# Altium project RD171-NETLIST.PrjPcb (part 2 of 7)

## Sheet 3.SchDoc
size 420 x 297 mm
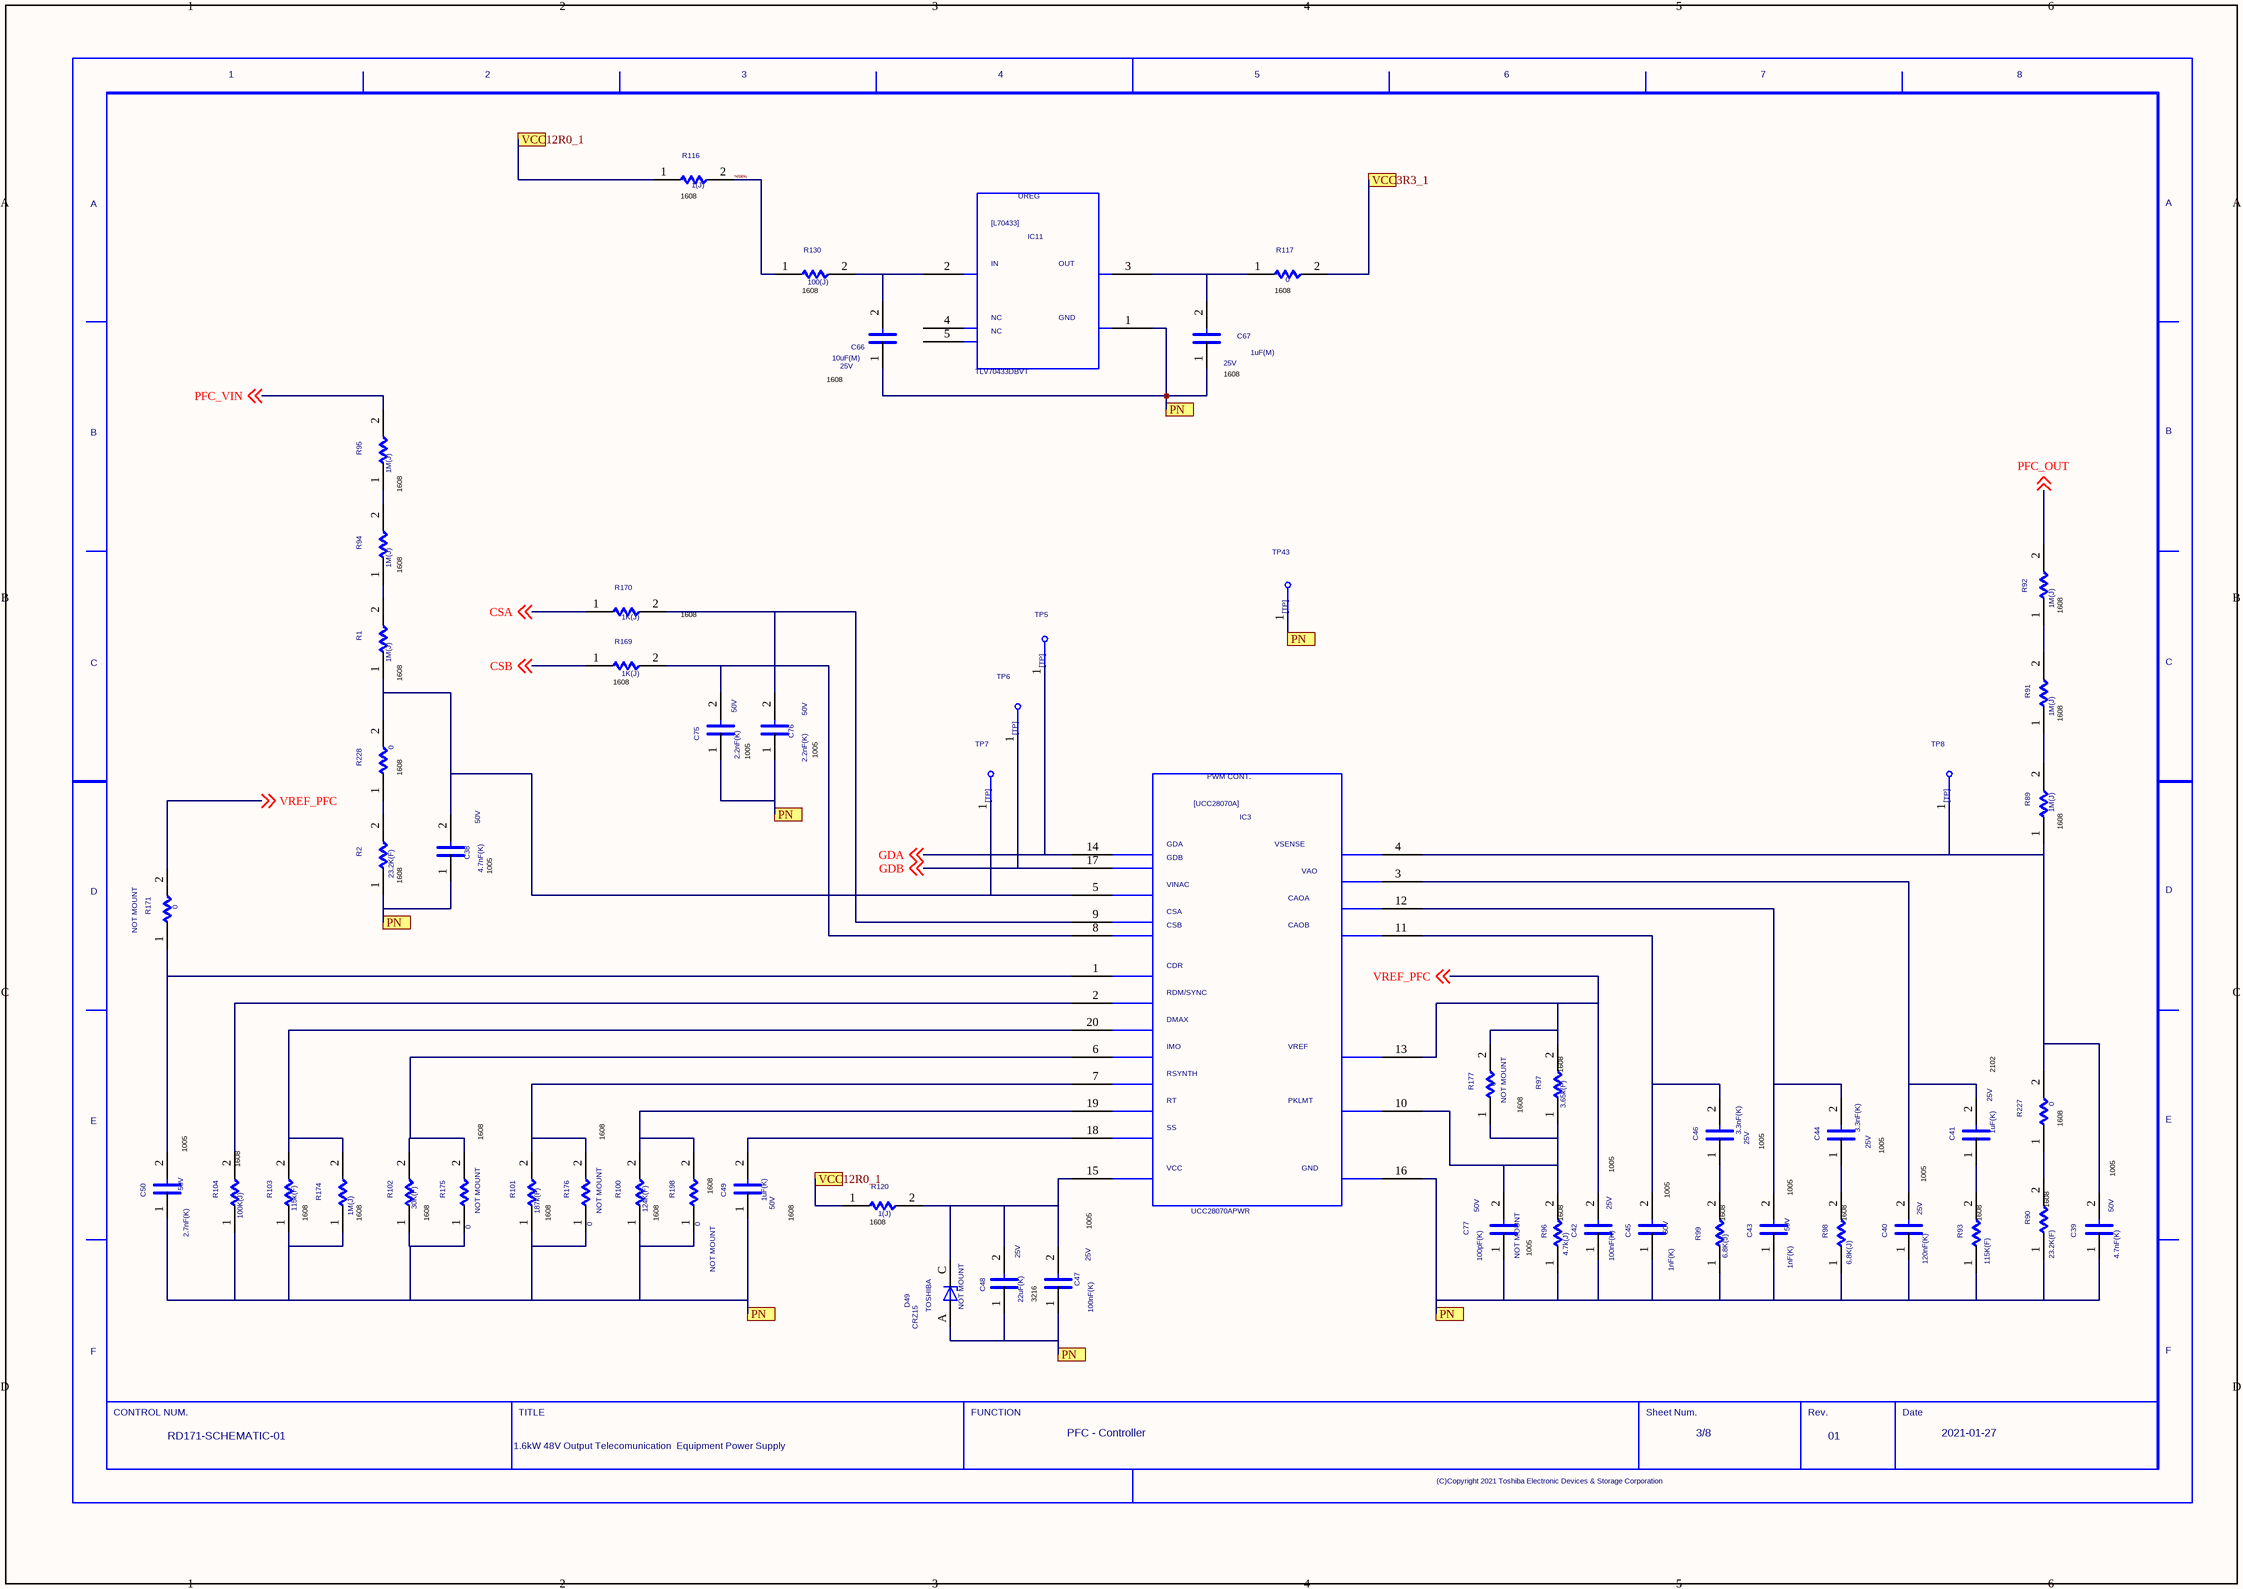
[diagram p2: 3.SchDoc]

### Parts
(Parts that share a designator on the sheet are numbered #1, #2 ... from top to bottom, then left to right.)
C38  VAL2: 50V  VAL1: 4.7nF(K)  (hidden comment: 4.7nF)
C39  VAL2: 50V  VAL1: 4.7nF(K)  (hidden comment: 4.7nF)
C40  VAL2: 25V  VAL1: 120nF(K)  (hidden comment: 120nF)
C41  VAL2: 25V  VAL1: 1uF(K)  (hidden comment: 1uF)
C42  VAL2: 25V  VAL1: 100nF(K)  (hidden comment: 100nF)
C43  VAL2: 50V  VAL1: 1nF(K)  (hidden comment: 1nF)
C44  VAL2: 25V  VAL1: 3.3nF(K)  (hidden comment: 3.3nF)
C45  VAL2: 50V  VAL1: 1nF(K)  (hidden comment: 1nF)
C46  VAL2: 25V  VAL1: 3.3nF(K)  (hidden comment: 3.3nF)
C47  VAL2: 25V  VAL1: 100nF(K)  (hidden comment: 100nF)
C48  VAL2: 25V  VAL1: 22uF(K)  (hidden comment: 22uF)
C49  VAL2: 50V  VAL1: 1uF(K)  [C1608JB1H105K080AB]  (hidden comment: 1uF)
C50  VAL2: 50V  VAL1: 2.7nF(K)  (hidden comment: 2.7nF)
C66  VAL2: 25V  VAL1: 10uF(M)  (hidden comment: 10uF)
C67  VAL2: 25V  VAL1: 1uF(M)  (hidden comment: 1uF)
C75  VAL2: 50V  VAL1: 2.2nF(K)  (hidden comment: 2.2nF)
C76  VAL2: 50V  VAL1: 2.2nF(K)  (hidden comment: 2.2nF)
C77  NOTMOUNT: NOT MOUNT  VAL2: 50V  VAL1: 100pF(K)  (hidden comment: 100pF)
D49  USERCOMPTEXT3: TOSHIBA  NOTMOUNT: NOT MOUNT  [CRZ15]  (hidden comment: D49)
IC3  IC3  [UCC28070APWR]  (value not drawn)
IC11  IC11  [TLV70433DBVT]  (value not drawn)
R1  VAL1: 1M(J)  (hidden comment: 1M)
R2  VAL1: 23.2K(F)  (hidden comment: 23.2K)
R89  VAL1: 1M(J)  (hidden comment: 1M)
R90  VAL1: 23.2K(F)  (hidden comment: 23.2K)
R91  VAL1: 1M(J)  (hidden comment: 1M)
R92  VAL1: 1M(J)  (hidden comment: 1M)
R93  VAL1: 115K(F)  (hidden comment: 115k)
R94  VAL1: 1M(J)  (hidden comment: 1M)
R95  VAL1: 1M(J)  (hidden comment: 1M)
R96  VAL1: 4.7k(J)  (hidden comment: 4.3k)
R97  VAL1: 3.65k(F)  (hidden comment: 3.65k)
R98  VAL1: 6.8K(J)  (hidden comment: 6.8k)
R99  VAL1: 6.8K(J)  (hidden comment: 6.8k)
R100  VAL1: 124K(F)  (hidden comment: 124k)
R101  VAL1: 187k(F)  (hidden comment: 187k)
R102  VAL1: 30K(F)  (hidden comment: 30k)
R103  VAL1: 115k(F)  (hidden comment: 115k)
R104  VAL1: 100K(J)  (hidden comment: 100k)
R116  VAL1: 1(J)  (hidden comment: 1)
R117  0
R120  VAL1: 1(J)  (hidden comment: 1)
R130  VAL1: 100(J)  (hidden comment: 100)
R169  VAL1: 1K(J)  (hidden comment: 1K)
R170  VAL1: 1K(J)  (hidden comment: 1K)
R171  NOTMOUNT: NOT MOUNT  (hidden comment: 0)
R174  VAL1: 1M(J)  (hidden comment: 1M)
R175  NOTMOUNT: NOT MOUNT  (hidden comment: 0)
R176  NOTMOUNT: NOT MOUNT  (hidden comment: 0)
R177  NOTMOUNT: NOT MOUNT  (hidden comment: 0)
R198  NOTMOUNT: NOT MOUNT  (hidden comment: 0)
R227  0
R228  0
TP5  TP5  [HK-2-S]  (value not drawn)
TP6  TP6  [HK-2-S]  (value not drawn)
TP7  TP7  [HK-2-S]  (value not drawn)
TP8  TP8  [HK-2-S]  (value not drawn)
TP43  TP43  [LC-22-S-WHITE]  (value not drawn)
U?#3  DATE: 2021-01-27  REVISION: 01  SHEETNUMBER: 3/8  FUNCTION: PFC - Controller  TITLE: 1.6kW 48V Output Telecomunication / Equipment Power Supply  DRAWINGNUMBER: RD171-SCHEMATIC-01  (hidden comment: WAKU_DEF100)

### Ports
PN, VCC3R3_1, VCC12R0_1

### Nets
$BN000001: R90.2 R227.1
$BN000002: R2.2 R228.1
CSA: R170.1 ; off-sheet CSA
CSB: R169.1 ; off-sheet CSB
GDA: IC3.14 TP5.1 ; off-sheet GDA
GDB: IC3.17 TP6.1 ; off-sheet GDB
N03591: R116.2 R130.1
PFC_OUT: R92.2 ; off-sheet PFC_OUT
PFC_VIN: R95.2 ; off-sheet PFC_VIN
SIG39: R89.2 R91.1
SIG40: R91.2 R92.1
SIG43: C45.2 C46.2 IC3.11
SIG44: C46.1 R99.2
SIG45: C43.2 C44.2 IC3.12
SIG46: C44.1 R98.2
SIG47: C40.2 C41.2 IC3.3
SIG48: C41.1 R93.2
SIG49: C39.2 IC3.4 R89.1 R227.2 TP8.1
SIG50: C49.2 IC3.18
SIG51: C50.2 IC3.1 R171.1
SIG52: IC3.19 R100.2 R198.2
SIG53: IC3.7 R101.2 R176.2
SIG54: IC3.6 R102.2 R175.2
SIG55: IC3.20 R103.2 R174.2
SIG56: IC3.2 R104.2
SIG60: R94.2 R95.1
SIG61: R1.2 R94.1
SIG62: C38.2 IC3.5 R1.1 R228.2 TP7.1
SIG86: C47.2 C48.2 D49.C IC3.15 R120.2
SIG185: C67.2 IC11.3 R117.1
SIG223: C66.2 IC11.2 R130.2
SIGN256: C77.2 IC3.10 R96.2 R97.1 R177.1
SIGN260: C76.2 IC3.9 R170.2
SIGN262: C75.2 IC3.8 R169.2
VREF_PFC: C42.2 IC3.13 R97.2 R171.2 R177.2 ; off-sheet VREF_PFC
NetC1_1: C38.1 C39.1 C40.1 C42.1 C43.1 C45.1 C47.1 C48.1 C49.1 C50.1 C66.1 C67.1 C75.1 C76.1 C77.1 D49.A IC3.16 IC11.1 R2.1 R90.1 R93.1 R96.1 R98.1 R99.1 R100.1 R101.1 R102.1 R103.1 R104.1 R174.1 R175.1 R176.1 R198.1 TP43.1 ; port PN
NetC70_2: R116.1 R120.1 ; port VCC12R0_1
NetC95_2: R117.2 ; port VCC3R3_1

Not connected (* = marked no-connect by the designer): IC11 4 5

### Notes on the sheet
- (near R116) 1608
- (near R130) 1608
- (near R117) 1608
- 1608
- (near C67) 1608
- (near R95) 1608
- (near R94) 1608
- (near R92) 1608
- (near R1) 1608
- (near R169) 1608
- (near R91) 1608
- (near R228) 1608
- 1005
- (near C76) 1005
- (near C38) 1005
- (near R89) 1608
- (near R2) 1608
- (near R97) 1608
- 2102
- (near R227) 1608
- (near C50) 1005
- (near R104) 1608
- (near R198) 1608
- (near C45) 1005
- (near C46) 1005
- (near C43) 1005
- (near C44) 1005
- (near R90) 1608
- (near C39) 1005
- (near R103) 1608
- (near R174) 1608
- (near R102) 1608
- (near R101) 1608
- (near R100) 1608
- (near C49) 1608
- (near R120) 1608
- (near R96) 1608
- (near R99) 1608
- (near R98) 1608
- (near R93) 1608
- 3216

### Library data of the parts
C38 = C: PARTNAME: Chip1005_GS_2; ORIGINALSYMBOLORIGIN: (0,0); TIME: 16:40:04; UPDATEUSER: t5459927; SAVECOUNT: 1; QUADMODEL: CON_1.2N; FUNCTION: C_C.Normal_package; NOMINALCAPACITA: 1.2n; RATEDVOLTAGE: 50; CDMASTERCADCELG: KC0005; MAKER: TDK; TEMPCHARACTERI2: B; SIZECODESMD: 1005; OUMEMAKER: TYD 太陽誘電; COMP: PRT_52; ADSMODELNAME: s_UMK105BJ122KV_F; PMPRODUCTSTYPEG: HD1; FNLEADFREETHET1GT2GMCTH1: 2_0_N; VAL3: GRM155R71H472JA01D; CAPACITANCETOLE: K; OUMECLASSIFICATION: セラミックコンデンサ; OUMEMAKERKATAMEI: UMK105BJ122KV-F; INSTANCENAME: INS2671
C39 = C: PARTNAME: Chip1005_GS_2; ORIGINALSYMBOLORIGIN: (0,0); TIME: 16:40:04; UPDATEUSER: t5459927; SAVECOUNT: 1; QUADMODEL: CON_1.2N; FUNCTION: C_C.Normal_package; NOMINALCAPACITA: 1.2n; RATEDVOLTAGE: 50; CDMASTERCADCELG: KC0005; MAKER: TDK; TEMPCHARACTERI2: B; SIZECODESMD: 1005; OUMEMAKER: TYD 太陽誘電; COMP: PRT_52; ADSMODELNAME: s_UMK105BJ122KV_F; PMPRODUCTSTYPEG: HD1; FNLEADFREETHET1GT2GMCTH1: 2_0_N; VAL3: GRM155R71H472JA01D; CAPACITANCETOLE: K; OUMECLASSIFICATION: セラミックコンデンサ; OUMEMAKERKATAMEI: UMK105BJ122KV-F; INSTANCENAME: INS2681
C40 = C: PARTNAME: Chip1608_GS_1; ORIGINALSYMBOLORIGIN: (0,0); TIME: 16:40:04; UPDATEUSER: t5459927; SAVECOUNT: 1; QUADMODEL: CON_150N; FUNCTION: C_C.Normal_package; NOMINALCAPACITA: 150n; RATEDVOLTAGE: 25; CDMASTERCADCELG: KC0008; MAKER: MURATA; SIZECODESMD: 1608; OUMEMAKER: MRT 村田製作所; COMP: PRT_48; ADSMODELNAME: s_GCM188R71E154KA37D; PMPRODUCTSTYPEG: DME; FNLEADFREETHET1GT2GMCTH1: N_N_N; VAL3: GRM188R71E124KA01D; CAPACITANCETOLE: K; OUMECLASSIFICATION: セラミックコンデンサ; OUMEMAKERKATAMEI: GCM188R71E154KA37D; INSTANCENAME: INS2519
C41 = C: PARTNAME: Chip2012_GS_1; ORIGINALSYMBOLORIGIN: (0,0); TIME: 16:40:04; UPDATEUSER: t5459927; SAVECOUNT: 1; COMPONENTNAME: C_C.Normal_package; RATEDVOLTAGE: 50; ADSMODELNAME: s_GCM31CR71H155KA55L; CAPACITANCETOLE: K; NOMINALCAPACITA: 1.5u; VAL3: C2012X7R1E105K125AB; MAKER: TDK; PMPRODUCTSTYPEG: DME; COMP: PRT_32; CHIPSIZE: 2012; INSTANCENAME: INS2529
C42 = C: PARTNAME: Chip1005_GS_2; ORIGINALSYMBOLORIGIN: (0,0); TIME: 16:40:04; UPDATEUSER: t5459927; SAVECOUNT: 1; QUADMODEL: CON_100N; FUNCTION: C_C.Normal_package; NOMINALCAPACITA: 100n; RATEDVOLTAGE: 25; CDMASTERCADCELG: KC0005; MAKER: TDK; SIZECODESMD: 1005; OUMEMAKER: MRT 村田製作所; COMP: PRT_52; ADSMODELNAME: s_GRM155R71E104KE14D; FNLEADFREETHET1GT2GMCTH1: N_N_N; VAL3: C1005X7R1E104K050BB; CAPACITANCETOLE: K; OUMECLASSIFICATION: セラミックコンデンサ; OUMEMAKERKATAMEI: GRM155R71E104KE14D; INSTANCENAME: INS2499
C43 = C: PARTNAME: Chip1005_GS_2; ORIGINALSYMBOLORIGIN: (0,0); TIME: 16:40:04; UPDATEUSER: t5459927; SAVECOUNT: 1; QUADMODEL: CON_1N; FUNCTION: C_C.Normal_package; NOMINALCAPACITA: 1n; RATEDVOLTAGE: 50; CDMASTERCADCELG: KC0005; MAKER: TDK; TEMPCHARACTERI2: B; SIZECODESMD: 1005; OUMEMAKER: TYD 太陽誘電; COMP: PRT_52; ADSMODELNAME: s_UMK105BJ102KV_F; PMPRODUCTSTYPEG: HD1-PC1; FNLEADFREETHET1GT2GMCTH1: 2_0_N; VAL3: UMK105BJ102KV-F; CAPACITANCETOLE: K; OUMECLASSIFICATION: セラミックコンデンサ; INSTANCENAME: INS2651
C44 = C: PARTNAME: Chip1005_GS_2; ORIGINALSYMBOLORIGIN: (0,0); TIME: 16:40:04; UPDATEUSER: t5459927; SAVECOUNT: 1; QUADMODEL: CON_3.3N; FUNCTION: C_C.Normal_package; NOMINALCAPACITA: 3.3n; RATEDVOLTAGE: 25; CDMASTERCADCELG: KC0005; MAKER: TDK; SIZECODESMD: 1005; OUMEMAKER: TDK ＴＤＫ; COMP: PRT_52; ADSMODELNAME: s_C1005JB1E332KT; FNLEADFREETHET1GT2GMCTH1: N_N_N; VAL3: CGJ2B2X7R1E332K050BA; CAPACITANCETOLE: K; OUMECLASSIFICATION: セラミックコンデンサ; OUMEMAKERKATAMEI: C1005JB1E332KT; INSTANCENAME: INS2893
C45 = C: PARTNAME: Chip1005_GS_2; ORIGINALSYMBOLORIGIN: (0,0); TIME: 16:40:04; UPDATEUSER: t5459927; SAVECOUNT: 1; QUADMODEL: CON_1N; FUNCTION: C_C.Normal_package; NOMINALCAPACITA: 1n; RATEDVOLTAGE: 50; CDMASTERCADCELG: KC0005; MAKER: TDK; TEMPCHARACTERI2: B; SIZECODESMD: 1005; OUMEMAKER: TYD 太陽誘電; COMP: PRT_52; ADSMODELNAME: s_UMK105BJ102KV_F; PMPRODUCTSTYPEG: HD1-PC1; FNLEADFREETHET1GT2GMCTH1: 2_0_N; VAL3: UMK105BJ102KV-F; CAPACITANCETOLE: K; OUMECLASSIFICATION: セラミックコンデンサ; INSTANCENAME: INS2661
C46 = C: PARTNAME: Chip1005_GS_2; ORIGINALSYMBOLORIGIN: (0,0); TIME: 16:40:04; UPDATEUSER: t5459927; SAVECOUNT: 1; QUADMODEL: CON_3.3N; FUNCTION: C_C.Normal_package; NOMINALCAPACITA: 3.3n; RATEDVOLTAGE: 25; CDMASTERCADCELG: KC0005; MAKER: TDK; SIZECODESMD: 1005; OUMEMAKER: TDK ＴＤＫ; COMP: PRT_52; ADSMODELNAME: s_C1005JB1E332KT; FNLEADFREETHET1GT2GMCTH1: N_N_N; VAL3: CGJ2B2X7R1E332K050BA; CAPACITANCETOLE: K; OUMECLASSIFICATION: セラミックコンデンサ; OUMEMAKERKATAMEI: C1005JB1E332KT; INSTANCENAME: INS2883
C47 = C: PARTNAME: Chip1005_GS_2; ORIGINALSYMBOLORIGIN: (0,0); TIME: 16:40:04; UPDATEUSER: t5459927; SAVECOUNT: 1; QUADMODEL: CON_100N; FUNCTION: C_C.Normal_package; NOMINALCAPACITA: 100n; RATEDVOLTAGE: 25; CDMASTERCADCELG: KC0005; MAKER: TDK; SIZECODESMD: 1005; OUMEMAKER: MRT 村田製作所; ADSCNVFLAG: ON; ADSCOMPONENTNAME: C_1005; COMP: PRT_52; ADSMODELNAME: s_GRM155R71E104KE14D; FNLEADFREETHET1GT2GMCTH1: N_N_N; VAL3: C1005X7R1E104K050BB; CAPACITANCETOLE: K; OUMECLASSIFICATION: セラミックコンデンサ; OUMEMAKERKATAMEI: GRM155R71E104KE14D; INSTANCENAME: INS2489
C48 = C: PARTNAME: Chip3216_GS_1; ORIGINALSYMBOLORIGIN: (0,0); TIME: 16:40:04; UPDATEUSER: t5459927; SAVECOUNT: 1; QUADMODEL: CON_22U; FUNCTION: C_C.Normal_package; NOMINALCAPACITA: 22u; RATEDVOLTAGE: 25; CDMASTERCADCELG: KC0014; MAKER: MURATA; TEMPCHARACTERI2: B; SIZECODESMD: 3216; OUMEMAKER: MRT 村田製作所; COMP: PRT_51; ADSMODELNAME: s_GRM31CB31E226ME15D; FNLEADFREETHET1GT2GMCTH1: N_N_N; VAL3: GRM31CR61E226KE15L; CAPACITANCETOLE: M; OUMECLASSIFICATION: セラミックコンデンサ; OUMEMAKERKATAMEI: GRM31CB31E226ME15D; INSTANCENAME: INS2863
C49 = C: PARTNAME: Chip1608_GS_1; ORIGINALSYMBOLORIGIN: (0,0); TIME: 16:40:04; UPDATEUSER: t5459927; SAVECOUNT: 1; QUADMODEL: CON_100N; FUNCTION: C_C.Normal_package; NOMINALCAPACITA: 100n; RATEDVOLTAGE: 25; CDMASTERCADCELG: KC0005; MAKER: TDK; SIZECODESMD: 1005; OUMEMAKER: MRT 村田製作所; COMP: PRT_52; ADSMODELNAME: s_GRM155R71E104KE14D; FNLEADFREETHET1GT2GMCTH1: N_N_N; CAPACITANCETOLE: K; OUMECLASSIFICATION: セラミックコンデンサ; OUMEMAKERKATAMEI: GRM155R71E104KE14D; INSTANCENAME: INS2479
C50 = C: PARTNAME: Chip1005_GS_2; ORIGINALSYMBOLORIGIN: (0,0); TIME: 16:40:04; UPDATEUSER: t5459927; SAVECOUNT: 1; QUADMODEL: CON_2.7N; FUNCTION: C_C.Normal_package; NOMINALCAPACITA: 2.7n; RATEDVOLTAGE: 50; CDMASTERCADCELG: DC834K; MAKER: TDK; TEMPCHARACTERI2: B; SIZECODESMD: 1005; OUMEMAKER: TYD 太陽誘電; COMP: PRT_52; ADSMODELNAME: s_UMK105BJ272KV_F; PMPRODUCTSTYPEG: PC1; FNLEADFREETHET1GT2GMCTH1: 3_0_N; VAL3: UMK105BJ272KV-F; CAPACITANCETOLE: K; OUMECLASSIFICATION: セラミックコンデンサ; INSTANCENAME: INS2711
C66 = C: PARTNAME: Chip1608_GS_1; ORIGINALSYMBOLORIGIN: (0,0); TIME: 16:40:04; UPDATEUSER: t5459927; SAVECOUNT: 1; QUADMODEL: CON_10U; FUNCTION: C_C.Normal_package; NOMINALCAPACITA: 10u; RATEDVOLTAGE: 25; CDMASTERCADCELG: KC0167; MAKER: TDK; SIZECODESMD: 1608; OUMEMAKER: MRT 村田製作所; COMP: PRT_48; ADSMODELNAME: s_ZRB18AR61E106ME01L; FNLEADFREETHET1GT2GMCTH1: N_N_N; VAL3: C1608X5R1E106M080AC; CAPACITANCETOLE: M; OUMECLASSIFICATION: セラミックコンデンサ; OUMEMAKERKATAMEI: ZRB18AR61E106ME01L; INSTANCENAME: INS2953
C67 = C: PARTNAME: Chip1005_GS_2; ORIGINALSYMBOLORIGIN: (0,0); TIME: 16:40:04; UPDATEUSER: t5459927; SAVECOUNT: 1; QUADMODEL: CON_1U; FUNCTION: C_C.Normal_package; NOMINALCAPACITA: 1u; RATEDVOLTAGE: 25; CDMASTERCADCELG: KC0008; MAKER: TDK; TEMPCHARACTERI2: B; SIZECODESMD: 1608; OUMEMAKER: MRT 村田製作所; ADSCNVFLAG: ON; ADSCOMPONENTNAME: C_1608; COMP: PRT_52; ADSMODELNAME: s_GRM185B31E105KA12D; PMPRODUCTSTYPEG: HD1; FNLEADFREETHET1GT2GMCTH1: N_N_N; VAL3: C1005X5R1E105M050BC; CAPACITANCETOLE: K; OUMECLASSIFICATION: セラミックコンデンサ; OUMEMAKERKATAMEI: GRM185B31E105KA12D; CHIPSIZE: 1005; INSTANCENAME: INS2963
C75 = C: PARTNAME: Chip1005_GS_2; ORIGINALSYMBOLORIGIN: (0,0); TIME: 16:40:04; UPDATEUSER: t5459927; SAVECOUNT: 1; QUADMODEL: CON_2.2N; FUNCTION: C_C.Normal_package; NOMINALCAPACITA: 2.2n; RATEDVOLTAGE: 50; CDMASTERCADCELG: KC0005; MAKER: TDK; TEMPCHARACTERI2: B; SIZECODESMD: 1005; OUMEMAKER: TYD 太陽誘電; COMP: PRT_52; ADSMODELNAME: s_UMK105BJ222KV_F; PMPRODUCTSTYPEG: HD1-PC1; FNLEADFREETHET1GT2GMCTH1: 2_0_N; VAL3: UMK105BJ222KV-F; CAPACITANCETOLE: K; OUMECLASSIFICATION: セラミックコンデンサ; INSTANCENAME: INS2691
C76 = C: PARTNAME: Chip1005_GS_2; ORIGINALSYMBOLORIGIN: (0,0); TIME: 16:40:04; UPDATEUSER: t5459927; SAVECOUNT: 1; QUADMODEL: CON_2.2N; FUNCTION: C_C.Normal_package; NOMINALCAPACITA: 2.2n; RATEDVOLTAGE: 50; CDMASTERCADCELG: KC0005; MAKER: TDK; OLDCOMPONENTID: 99; TEMPCHARACTERI2: B; SIZECODESMD: 1005; OUMEMAKER: TYD 太陽誘電; COMP: PRT_52; ADSMODELNAME: s_UMK105BJ222KV_F; PMPRODUCTSTYPEG: HD1-PC1; FNLEADFREETHET1GT2GMCTH1: 2_0_N; VAL3: UMK105BJ222KV-F; CAPACITANCETOLE: K; OUMECLASSIFICATION: セラミックコンデンサ; INSTANCENAME: INS2701
C77 = C: PARTNAME: Chip1608_GS_1; ORIGINALSYMBOLORIGIN: (0,0); TIME: 16:40:04; UPDATEUSER: t5459927; SAVECOUNT: 1; COMP: PRT_48; CHIPSIZE: 1608; FUNCTION: C_C.Normal_package; VAL3: GRM1885C1H101JA01D; MAKER: MURATA; INSTANCENAME: INS2539
D49 = ZD: PARTNAME: CRZ15_TS_A; OUMEPARTTYPE: D; UPDATEUSER: t5459927; UPDATETIME: 16:40:05; SAVECOUNT: 1; SAVEAREA0: -4630,-153,17114,13055; ORIGINALSYMBOLORIGIN: (0,0); FUNCTION: ZD_ZD.Normal_package; CDMASTERCADCELG: MMK0167; FORWARDVOLTAGEM: 0; OUMEMAKER: TSB 東芝; MOUNTINGFORMSMD: SMD; COMP: PRT_6; ADSMODELNAME: s_CRZ15; FNLEADFREETHET1GT2GMCTH1: N_N_N; ZENERVOLTAGEMAX: 16.5; OUMECLASSIFICATION: 定電圧ダイオード; INSTANCENAME: INS2465
IC3 = L28070: PARTNAME: UCC28070APW_TI; UPDATEUSER: t5459927; UPDATETIME: 16:40:04; SAVECOUNT: 1; SAVEAREA0: -70831,-61057,118891,26398; ORIGINALSYMBOLORIGIN: (0,0); COMP: PRT_59; FUNCTION: L28070_L28070.Normal_package; MAKER: TEXAS; INSTANCENAME: INS2419
IC11 = L70433: PARTNAME: TLV70433DBVT_TI; UPDATEUSER: t5459927; UPDATETIME: 16:40:04; SAVECOUNT: 1; SAVEAREA0: -25132,-24804,51942,10724; ORIGINALSYMBOLORIGIN: (0,0); COMP: PRT_10; FUNCTION: L70433_L70433.Normal_package; MAKER: TEXAS; INSTANCENAME: INS3049
R1 = R: PARTNAME: Chip1608_GS_1; ORIGINALSYMBOLORIGIN: (0,0); TIME: 16:40:04; UPDATEUSER: t5459927; SAVECOUNT: 1; QUADMODEL: RES_1M; FUNCTION: R_R.Normal_package; CDMASTERCADCELG: KC0167; MAKER: KOA; RESISTANCETOLER: F; SIZECODESMD: 1608; OUMEMAKER: KOA コーア; POWERRATING: 100m; MOUNTINGFORMSMD: SMD; COMP: PRT_8; ADSMODELNAME: s_RK73H1JTTD1004F; FNLEADFREETHET1GT2GMCTH1: N_N_N; VAL3: RK73B1JTTD105J; VAL2: 100mW,±5%; OUMECLASSIFICATION: 表面実装用固定抵抗器; OUMEMAKERKATAMEI: RK73H1JTTD1004F; INSTANCENAME: INS2763
R2 = R: PARTNAME: Chip1608_GS_1; ORIGINALSYMBOLORIGIN: (0,0); TIME: 16:40:04; UPDATEUSER: t5459927; SAVECOUNT: 1; QUADMODEL: RES_24K; FUNCTION: R_R.Normal_package; CDMASTERCADCELG: KC0008; MAKER: PANASONIC; RESISTANCETOLER: J; SIZECODESMD: 1608; OUMEMAKER: NAE パナソニックエレクトロニックデバイス; POWERRATING: 63m; MOUNTINGFORMSMD: SMD; NOMINALRESISTAN: 24K; COMP: PRT_8; ADSMODELNAME: s_ERJ3GEYJ243V; FNLEADFREETHET1GT2GMCTH1: 3_1_N; VAL3: ERJ-3EKF2322V; VAL2: 100mW,±1%; OUMECLASSIFICATION: 表面実装用固定抵抗器; OUMEMAKERKATAMEI: ERJ3GEYJ243V; INSTANCENAME: INS2773
R89 = R: PARTNAME: Chip1608_GS_1; ORIGINALSYMBOLORIGIN: (0,0); TIME: 16:40:04; UPDATEUSER: t5459927; SAVECOUNT: 1; QUADMODEL: RES_1M; FUNCTION: R_R.Normal_package; CDMASTERCADCELG: KC0167; MAKER: KOA; RESISTANCETOLER: F; SIZECODESMD: 1608; OUMEMAKER: KOA コーア; POWERRATING: 100m; MOUNTINGFORMSMD: SMD; COMP: PRT_8; ADSMODELNAME: s_RK73H1JTTD1004F; FNLEADFREETHET1GT2GMCTH1: N_N_N; VAL3: RK73B1JTTD105J; VAL2: 100mW; OUMECLASSIFICATION: 表面実装用固定抵抗器; OUMEMAKERKATAMEI: RK73H1JTTD1004F; INSTANCENAME: INS2813
R90 = R: PARTNAME: Chip1608_GS_1; ORIGINALSYMBOLORIGIN: (0,0); TIME: 16:40:04; UPDATEUSER: t5459927; SAVECOUNT: 1; QUADMODEL: RES_22K; FUNCTION: R_R.Normal_package; CDMASTERCADCELG: KC0008; MAKER: PANASONIC; RESISTANCETOLER: F; SIZECODESMD: 1608; OUMEMAKER: NAE パナソニックエレクトロニックデバイス; POWERRATING: 100m; MOUNTINGFORMSMD: SMD; NOMINALRESISTAN: 22K; COMP: PRT_8; ADSMODELNAME: s_ERJ3EKF2202V; FNLEADFREETHET1GT2GMCTH1: N_N_N; VAL3: ERJ-3EKF2322V; VAL2: 100mW,±1%; OUMECLASSIFICATION: 表面実装用固定抵抗器; OUMEMAKERKATAMEI: ERJ3EKF2202V; INSTANCENAME: INS2923
R91 = R: PARTNAME: Chip1608_GS_1; ORIGINALSYMBOLORIGIN: (0,0); TIME: 16:40:04; UPDATEUSER: t5459927; SAVECOUNT: 1; QUADMODEL: RES_1M; FUNCTION: R_R.Normal_package; CDMASTERCADCELG: KC0167; MAKER: KOA; RESISTANCETOLER: F; SIZECODESMD: 1608; OUMEMAKER: KOA コーア; POWERRATING: 100m; MOUNTINGFORMSMD: SMD; COMP: PRT_8; ADSMODELNAME: s_RK73H1JTTD1004F; FNLEADFREETHET1GT2GMCTH1: N_N_N; VAL3: RK73B1JTTD105J; VAL2: 100mW,±5%; OUMECLASSIFICATION: 表面実装用固定抵抗器; OUMEMAKERKATAMEI: RK73H1JTTD1004F; INSTANCENAME: INS2803
R92 = R: PARTNAME: Chip1608_GS_1; ORIGINALSYMBOLORIGIN: (0,0); TIME: 16:40:04; UPDATEUSER: t5459927; SAVECOUNT: 1; QUADMODEL: RES_1M; FUNCTION: R_R.Normal_package; CDMASTERCADCELG: KC0167; MAKER: KOA; RESISTANCETOLER: F; SIZECODESMD: 1608; OUMEMAKER: KOA コーア; POWERRATING: 100m; MOUNTINGFORMSMD: SMD; COMP: PRT_8; ADSMODELNAME: s_RK73H1JTTD1004F; FNLEADFREETHET1GT2GMCTH1: N_N_N; VAL3: RK73B1JTTD105J; VAL2: 100mW,±5%; OUMECLASSIFICATION: 表面実装用固定抵抗器; OUMEMAKERKATAMEI: RK73H1JTTD1004F; INSTANCENAME: INS2823
R93 = R: PARTNAME: Chip1608_GS_1; ORIGINALSYMBOLORIGIN: (0,0); TIME: 16:40:04; UPDATEUSER: t5459927; SAVECOUNT: 1; QUADMODEL: RES_110K; FUNCTION: R_R.Normal_package; CDMASTERCADCELG: KC0008; MAKER: PANASONIC; RESISTANCETOLER: F; SIZECODESMD: 1608; OUMEMAKER: NAE パナソニックエレクトロニックデバイス; POWERRATING: 100m; MOUNTINGFORMSMD: SMD; NOMINALRESISTAN: 110K; COMP: PRT_8; ADSMODELNAME: s_ERJ3EKF1103V; FNLEADFREETHET1GT2GMCTH1: N_N_N; VAL3: ERJ-3EKF1153V; VAL2: 100mW,±1%; OUMECLASSIFICATION: 表面実装用固定抵抗器; OUMEMAKERKATAMEI: ERJ3EKF1103V; INSTANCENAME: INS2913
R94 = R: PARTNAME: Chip1608_GS_1; ORIGINALSYMBOLORIGIN: (0,0); TIME: 16:40:04; UPDATEUSER: t5459927; SAVECOUNT: 1; QUADMODEL: RES_1M; FUNCTION: R_R.Normal_package; CDMASTERCADCELG: KC0167; MAKER: KOA; RESISTANCETOLER: F; SIZECODESMD: 1608; OUMEMAKER: KOA コーア; POWERRATING: 100m; MOUNTINGFORMSMD: SMD; COMP: PRT_8; ADSMODELNAME: s_RK73H1JTTD1004F; FNLEADFREETHET1GT2GMCTH1: N_N_N; VAL3: RK73B1JTTD105J; VAL2: 100mW,±5%; OUMECLASSIFICATION: 表面実装用固定抵抗器; OUMEMAKERKATAMEI: RK73H1JTTD1004F; INSTANCENAME: INS2743
R95 = R: PARTNAME: Chip1608_GS_1; ORIGINALSYMBOLORIGIN: (0,0); TIME: 16:40:04; UPDATEUSER: t5459927; SAVECOUNT: 1; QUADMODEL: RES_1M; FUNCTION: R_R.Normal_package; CDMASTERCADCELG: KC0167; MAKER: KOA; RESISTANCETOLER: F; SIZECODESMD: 1608; OUMEMAKER: KOA コーア; POWERRATING: 100m; MOUNTINGFORMSMD: SMD; COMP: PRT_8; ADSMODELNAME: s_RK73H1JTTD1004F; FNLEADFREETHET1GT2GMCTH1: N_N_N; VAL3: RK73B1JTTD105J; VAL2: 100mW,±5%; OUMECLASSIFICATION: 表面実装用固定抵抗器; OUMEMAKERKATAMEI: RK73H1JTTD1004F; INSTANCENAME: INS2753
R96 = R: PARTNAME: Chip1608_GS_1; ORIGINALSYMBOLORIGIN: (0,0); TIME: 16:40:04; UPDATEUSER: t5459927; SAVECOUNT: 1; COMP: PRT_8; CHIPSIZE: 1608; FUNCTION: R_R.Normal_package; VAL3: RK73B1JTTD392J; VAL2: 100mW,±5%; MAKER: KOA; INSTANCENAME: INS2571
R97 = R: PARTNAME: Chip1608_GS_1; ORIGINALSYMBOLORIGIN: (0,0); TIME: 16:40:04; UPDATEUSER: t5459927; SAVECOUNT: 1; COMP: PRT_8; CHIPSIZE: 1608; FUNCTION: R_R.Normal_package; VAL3: ERJ-3EKF3651V; VAL2: 100mW,±1%; MAKER: PANASONIC; INSTANCENAME: INS2561
R98 = R: PARTNAME: Chip1608_GS_1; ORIGINALSYMBOLORIGIN: (0,0); TIME: 16:40:04; UPDATEUSER: t5459927; SAVECOUNT: 1; QUADMODEL: RES_6.8K; FUNCTION: R_R.Normal_package; CDMASTERCADCELG: KCK0203; MAKER: KOA; RESISTANCETOLER: B; SIZECODESMD: 1608; OUMEMAKER: KOA コーア; POWERRATING: 100m; MOUNTINGFORMSMD: SMD; COMP: PRT_8; ADSMODELNAME: s_RN73H1JTTD6801B10; PMPRODUCTSTYPEG: DME; FNLEADFREETHET1GT2GMCTH1: N_N_N; VAL3: RK73B1JTTD682J; VAL2: 100mW,±5%; OUMECLASSIFICATION: 表面実装用固定抵抗器; OUMEMAKERKATAMEI: RN73H1JTTD6801B10; INSTANCENAME: INS2903
R99 = R: PARTNAME: Chip1608_GS_1; ORIGINALSYMBOLORIGIN: (0,0); TIME: 16:40:04; UPDATEUSER: t5459927; SAVECOUNT: 1; QUADMODEL: RES_6.8K; FUNCTION: R_R.Normal_package; CDMASTERCADCELG: KCK0203; MAKER: KOA; RESISTANCETOLER: B; SIZECODESMD: 1608; OUMEMAKER: KOA コーア; POWERRATING: 100m; MOUNTINGFORMSMD: SMD; COMP: PRT_8; ADSMODELNAME: s_RN73H1JTTD6801B10; PMPRODUCTSTYPEG: DME; FNLEADFREETHET1GT2GMCTH1: N_N_N; VAL3: RK73B1JTTD682J; VAL2: 100mW,±5%; OUMECLASSIFICATION: 表面実装用固定抵抗器; OUMEMAKERKATAMEI: RN73H1JTTD6801B10; INSTANCENAME: INS2873
R100 = R: PARTNAME: Chip1608_GS_1; ORIGINALSYMBOLORIGIN: (0,0); TIME: 16:40:04; UPDATEUSER: t5459927; SAVECOUNT: 1; QUADMODEL: RES_120K; FUNCTION: R_R.Normal_package; CDMASTERCADCELG: KC0008; MAKER: PANASONIC; RESISTANCETOLER: F; SIZECODESMD: 1608; OUMEMAKER: NAE パナソニックエレクトロニックデバイス; POWERRATING: 100m; MOUNTINGFORMSMD: SMD; NOMINALRESISTAN: 120K; COMP: PRT_8; ADSMODELNAME: s_ERJ3EKF1203V; FNLEADFREETHET1GT2GMCTH1: N_N_N; VAL3: ERJ-3EKF1243V; VAL2: 100mW,±1; OUMECLASSIFICATION: 表面実装用固定抵抗器; OUMEMAKERKATAMEI: ERJ3EKF1203V; INSTANCENAME: INS2853
R101 = R: PARTNAME: Chip1608_GS_1; ORIGINALSYMBOLORIGIN: (0,0); TIME: 16:40:04; UPDATEUSER: t5459927; SAVECOUNT: 1; COMP: PRT_8; CHIPSIZE: 1608; FUNCTION: R_R.Normal_package; VAL3: ERJ-3EKF1873V; VAL2: 100mW,±1%; MAKER: PANASONIC; INSTANCENAME: INS2581
R102 = R: PARTNAME: Chip1608_GS_1; ORIGINALSYMBOLORIGIN: (0,0); TIME: 16:40:04; UPDATEUSER: t5459927; SAVECOUNT: 1; QUADMODEL: RES_30K; FUNCTION: R_R.Normal_package; CDMASTERCADCELG: KC0008; MAKER: KOA; RESISTANCETOLER: B; SIZECODESMD: 1608; OUMEMAKER: KOA コーア; POWERRATING: 100m; MOUNTINGFORMSMD: SMD; COMP: PRT_8; ADSMODELNAME: s_RN73H1JTTD3002B10; FNLEADFREETHET1GT2GMCTH1: N_N_N; VAL3: RK73H1JTTD3002F; VAL2: 100mW,±1%; OUMECLASSIFICATION: 表面実装用固定抵抗器; OUMEMAKERKATAMEI: RN73H1JTTD3002B10; INSTANCENAME: INS2843
R103 = R: PARTNAME: Chip1608_GS_1; ORIGINALSYMBOLORIGIN: (0,0); TIME: 16:40:04; UPDATEUSER: t5459927; SAVECOUNT: 1; COMP: PRT_8; CHIPSIZE: 1608; FUNCTION: R_R.Normal_package; VAL3: ERJ-3EKF1153V; VAL2: 100mW,±1%; MAKER: PANASONIC; INSTANCENAME: INS2551
R104 = R: PARTNAME: Chip1608_GS_1; ORIGINALSYMBOLORIGIN: (0,0); TIME: 16:40:04; UPDATEUSER: t5459927; SAVECOUNT: 1; QUADMODEL: RES_100K; FUNCTION: R_R.Normal_package; CDMASTERCADCELG: KC0008; MAKER: KOA; RESISTANCETOLER: G; SIZECODESMD: 1608; OUMEMAKER: KOA コーア; POWERRATING: 100m; MOUNTINGFORMSMD: SMD; COMP: PRT_8; ADSMODELNAME: s_RK73B1JTTD104G; FNLEADFREETHET1GT2GMCTH1: N_N_N; VAL3: RK73B1JTTD104J; VAL2: 100mW,±5%; OUMECLASSIFICATION: 表面実装用固定抵抗器; OUMEMAKERKATAMEI: RK73B1JTTD104G; INSTANCENAME: INS2833
R116 = R: PARTNAME: Chip1608_GS_1; ORIGINALSYMBOLORIGIN: (0,0); TIME: 16:40:04; UPDATEUSER: t5459927; QUADMODEL: RES_1; FUNCTION: R_R.Normal_package; CDMASTERCADCELG: KC0008; MAKER: PANASONIC; RESISTANCETOLER: J; SIZECODESMD: 1608; OUMEMAKER: NAE パナソニックエレクトロニックデバイス; POWERRATING: 63m; MOUNTINGFORMSMD: SMD; COMP: PRT_8; ADSMODELNAME: s_ERJ3GEYJ1R0V; PMPRODUCTSTYPEG: PC1; FNLEADFREETHET1GT2GMCTH1: 2_1_N; VAL3: ERJ-3GEYJ1R0V; VAL2: 100mW,±5%; OUMECLASSIFICATION: 表面実装用固定抵抗器; OUMEMAKERKATAMEI: ERJ3GEYJ1R0V; INSTANCENAME: INS2943
R117 = R: PARTNAME: Chip1608_GS_1; ORIGINALSYMBOLORIGIN: (0,0); TIME: 16:40:04; UPDATEUSER: t5459927; SAVECOUNT: 1; QUADMODEL: RES_0; FUNCTION: R_R.Normal_package; CDMASTERCADCELG: KC0005; MAKER: KOA; RESISTANCETOLER: X; SIZECODESMD: 1005; OUMEMAKER: NAE パナソニックエレクトロニックデバイス; ADSCNVFLAG: ON; POWERRATING: 63m; MOUNTINGFORMSMD: SMD; ADSCOMPONENTNAME: R_1005; COMP: PRT_8; ADSMODELNAME: s_ERJ2GE0R00X; PMPRODUCTSTYPEG: HD1-PC1; FNLEADFREETHET1GT2GMCTH1: 2_1_N; VAL3: RK73Z1JTTD; VAL2: 100mW; OUMECLASSIFICATION: 表面実装用固定抵抗器; OUMEMAKERKATAMEI: ERJ2GE0R00X; CHIPSIZE: 1608; INSTANCENAME: INS2983
R120 = R: PARTNAME: Chip1608_GS_1; ORIGINALSYMBOLORIGIN: (0,0); TIME: 16:40:04; UPDATEUSER: t5459927; QUADMODEL: RES_1; FUNCTION: R_R.Normal_package; CDMASTERCADCELG: KC0008; MAKER: PANASONIC; RESISTANCETOLER: J; SIZECODESMD: 1608; OUMEMAKER: NAE パナソニックエレクトロニックデバイス; POWERRATING: 63m; MOUNTINGFORMSMD: SMD; COMP: PRT_8; ADSMODELNAME: s_ERJ3GEYJ1R0V; PMPRODUCTSTYPEG: PC1; FNLEADFREETHET1GT2GMCTH1: 2_1_N; VAL3: ERJ-3GEYJ1R0V; VAL2: 100mW,±5%; OUMECLASSIFICATION: 表面実装用固定抵抗器; OUMEMAKERKATAMEI: ERJ3GEYJ1R0V; INSTANCENAME: INS2509
R130 = R: PARTNAME: Chip1608_GS_1; ORIGINALSYMBOLORIGIN: (0,0); TIME: 16:40:04; UPDATEUSER: t5459927; SAVECOUNT: 1; QUADMODEL: RES_100; FUNCTION: R_R.Normal_package; CDMASTERCADCELG: KC0165; MAKER: KOA; RESISTANCETOLER: F; SIZECODESMD: 1608; OUMEMAKER: NAE パナソニックエレクトロニックデバイス; POWERRATING: 250m; MOUNTINGFORMSMD: SMD; COMP: PRT_8; ADSMODELNAME: s_ERJPA3F1000V@@; PMPRODUCTSTYPEG: DA; FNLEADFREETHET1GT2GMCTH1: N_N_N; VAL3: RK73B1JTTD101J; VAL2: 125mW,±5%; OUMECLASSIFICATION: 表面実装用固定抵抗器; OUMEMAKERKATAMEI: ERJPA3F1000V@@; INSTANCENAME: INS2973
R169 = R: PARTNAME: Chip1608_GS_1; ORIGINALSYMBOLORIGIN: (0,0); TIME: 16:40:04; UPDATEUSER: t5459927; SAVECOUNT: 1; QUADMODEL: RES_1K; FUNCTION: R_R.Normal_package; CDMASTERCADCELG: KCK0203; MAKER: KOA; RESISTANCETOLER: G; SIZECODESMD: 1608; OUMEMAKER: KOA コーア; POWERRATING: 100m; MOUNTINGFORMSMD: SMD; COMP: PRT_8; ADSMODELNAME: s_RK73B1JTTD102G; PMPRODUCTSTYPEG: DME; FNLEADFREETHET1GT2GMCTH1: N_N_N; VAL3: RK73B1JTTD102J; VAL2: 125mW,±5%; OUMECLASSIFICATION: 表面実装用固定抵抗器; OUMEMAKERKATAMEI: RK73B1JTTD102G; INSTANCENAME: INS2783
R170 = R: PARTNAME: Chip1608_GS_1; ORIGINALSYMBOLORIGIN: (0,0); TIME: 16:40:04; UPDATEUSER: t5459927; SAVECOUNT: 1; QUADMODEL: RES_1K; FUNCTION: R_R.Normal_package; CDMASTERCADCELG: KCK0203; MAKER: KOA; OLDCOMPONENTID: 100; RESISTANCETOLER: G; SIZECODESMD: 1608; OUMEMAKER: KOA コーア; POWERRATING: 100m; MOUNTINGFORMSMD: SMD; COMP: PRT_8; ADSMODELNAME: s_RK73B1JTTD102G; PMPRODUCTSTYPEG: DME; FNLEADFREETHET1GT2GMCTH1: N_N_N; VAL3: RK73B1JTTD102J; VAL2: 125mW,±5%; OUMECLASSIFICATION: 表面実装用固定抵抗器; OUMEMAKERKATAMEI: RK73B1JTTD102G; INSTANCENAME: INS2793
R171 = R: PARTNAME: Chip1608_GS_1; ORIGINALSYMBOLORIGIN: (0,0); TIME: 16:40:04; UPDATEUSER: t5459927; SAVECOUNT: 1; QUADMODEL: RES_0; FUNCTION: R_R.Normal_package; CDMASTERCADCELG: KCK0203; MAKER: KOA; RESISTANCETOLER: X; SIZECODESMD: 1608; OUMEMAKER: KOA コーア; POWERRATING: 100m; MOUNTINGFORMSMD: SMD; COMP: PRT_8; ADSMODELNAME: s_RK73Z1JTTD; PMPRODUCTSTYPEG: DME-HD1-PC1; FNLEADFREETHET1GT2GMCTH1: 3_2_N; VAL3: RK73Z1JTTD; VAL2: 100mW; OUMECLASSIFICATION: 表面実装用固定抵抗器; INSTANCENAME: INS2731
R174 = R: PARTNAME: Chip1608_GS_1; ORIGINALSYMBOLORIGIN: (0,0); TIME: 16:40:04; UPDATEUSER: t5459927; SAVECOUNT: 1; QUADMODEL: RES_1M; FUNCTION: R_R.Normal_package; CDMASTERCADCELG: KC0167; MAKER: KOA; RESISTANCETOLER: F; SIZECODESMD: 1608; OUMEMAKER: KOA コーア; POWERRATING: 100m; MOUNTINGFORMSMD: SMD; COMP: PRT_8; ADSMODELNAME: s_RK73H1JTTD1004F; FNLEADFREETHET1GT2GMCTH1: N_N_N; VAL3: RK73B1JTTD105J; VAL2: 100mW; OUMECLASSIFICATION: 表面実装用固定抵抗器; OUMEMAKERKATAMEI: RK73H1JTTD1004F; INSTANCENAME: INS16994302
R175 = R: PARTNAME: Chip1608_GS_1; ORIGINALSYMBOLORIGIN: (0,0); TIME: 16:40:04; UPDATEUSER: t5459927; SAVECOUNT: 1; COMP: PRT_8; CHIPSIZE: 1608; FUNCTION: R_R.Normal_package; VAL3: RK73Z1JTTD; VAL2: 100mW; MAKER: KOA; INSTANCENAME: INS2603
R176 = R: PARTNAME: Chip1608_GS_1; ORIGINALSYMBOLORIGIN: (0,0); TIME: 16:40:04; UPDATEUSER: t5459927; SAVECOUNT: 1; COMP: PRT_8; CHIPSIZE: 1608; FUNCTION: R_R.Normal_package; VAL3: RK73Z1JTTD; VAL2: 100mW; MAKER: KOA; INSTANCENAME: INS2615
R177 = R: PARTNAME: Chip1608_GS_1; ORIGINALSYMBOLORIGIN: (0,0); TIME: 16:40:04; UPDATEUSER: t5459927; SAVECOUNT: 1; COMP: PRT_8; CHIPSIZE: 1608; FUNCTION: R_R.Normal_package; VAL3: RK73Z1JTTD; VAL2: 100mW; MAKER: KOA; INSTANCENAME: INS2627
R198 = R: PARTNAME: Chip1608_GS_1; ORIGINALSYMBOLORIGIN: (0,0); TIME: 16:40:04; UPDATEUSER: t5459927; SAVECOUNT: 1; COMP: PRT_8; CHIPSIZE: 1608; FUNCTION: R_R.Normal_package; VAL3: RK73Z1JTTD; VAL2: 100mW; MAKER: KOA; INSTANCENAME: INS2639
R227 = R: PARTNAME: Chip1608_GS_1; ORIGINALSYMBOLORIGIN: (0,0); TIME: 16:40:04; UPDATEUSER: t5459927; SAVECOUNT: 1; COMP: PRT_8; CHIPSIZE: 1608; FUNCTION: R_R.Normal_package; VAL3: RK73H1JTTD6800F; VAL2: 100mW,±1%; MAKER: KOA; INSTANCENAME: INS2721
R228 = R: PARTNAME: Chip1608_GS_1; ORIGINALSYMBOLORIGIN: (0,0); TIME: 16:40:04; UPDATEUSER: t5459927; SAVECOUNT: 1; COMP: PRT_8; CHIPSIZE: 1608; FUNCTION: R_R.Normal_package; VAL3: RK73H1JTTD6800F; VAL2: 100mW,±1%; MAKER: KOA; INSTANCENAME: INS2933
TP5 = TP: PARTNAME: HK-2_M8; UPDATEUSER: t5459927; UPDATETIME: 16:40:05; SAVECOUNT: 1; SAVEAREA0: -242,-92,12810,7836; ORIGINALSYMBOLORIGIN: (0,0); COMPONENTNAME: TP_TP.Normal_package; ID: GDA; MAKER: MAC8; COMP: PRT_44; INSTANCENAME: INS3009
TP6 = TP: PARTNAME: HK-2_M8; UPDATEUSER: t5459927; UPDATETIME: 16:40:05; SAVECOUNT: 1; SAVEAREA0: -242,-92,12810,7836; ORIGINALSYMBOLORIGIN: (0,0); COMPONENTNAME: TP_TP.Normal_package; ID: GDB; MAKER: MAC8; COMP: PRT_44; INSTANCENAME: INS3001
TP7 = TP: PARTNAME: HK-2_M8; UPDATEUSER: t5459927; UPDATETIME: 16:40:05; SAVECOUNT: 1; SAVEAREA0: -242,-92,12810,7836; ORIGINALSYMBOLORIGIN: (0,0); COMPONENTNAME: TP_TP.Normal_package; ID: VINAC; MAKER: MAC8; COMP: PRT_44; INSTANCENAME: INS2993
TP8 = TP: PARTNAME: HK-2_M8; UPDATEUSER: t5459927; UPDATETIME: 16:40:05; SAVECOUNT: 1; SAVEAREA0: -242,-92,12810,7836; ORIGINALSYMBOLORIGIN: (0,0); COMPONENTNAME: TP_TP.Normal_package; ID: VSENSE; MAKER: MAC8; COMP: PRT_44; INSTANCENAME: INS3017
TP43 = TP: PARTNAME: LC-22_GS; UPDATEUSER: t5459927; UPDATETIME: 16:40:05; SAVECOUNT: 1; SAVEAREA0: -242,-92,12810,7836; ORIGINALSYMBOLORIGIN: (0,0); COMPONENTNAME: TP_TP.Normal_package; ID: PN; MAKER: MAC8; COMP: PRT_49; INSTANCENAME: INS3025
U?#3 = WAKU_DEF100: PLOTTIME: HH:MM; SAVEAREA0: 168739,-66042,466246,90057; TIME: 14:30:25; UPDATEUSER: t5459927; UPDATETIME: 15:16:57; SAVECOUNT: 5; OriginalSymbolOrigin: (10160,284480)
